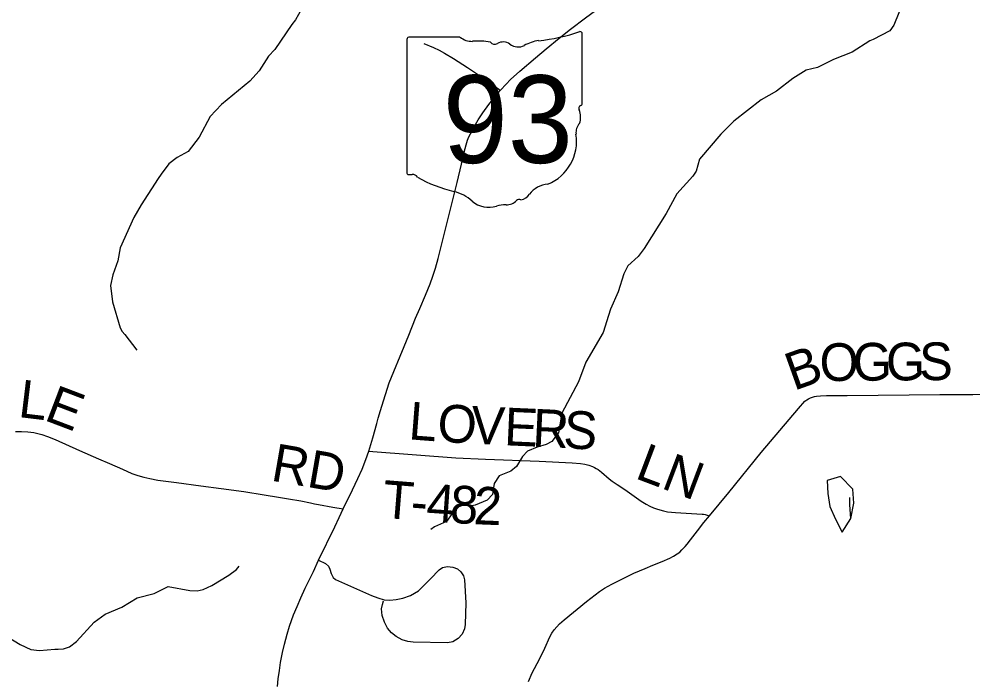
# Model space of a CAD drawing. Extents: x 0 to 34, y 0 to 22.
# Drawn here: x 2.781 to 4.217, y 16.645 to 17.641 of the extents above; entities that cross this region are included whole.
import ezdxf

# ---------------------------------------------------------------- set-up
doc = ezdxf.new("R2010")
doc.units = 0
for name, color, linetype in [('GM_X_County_Road', 7, 'Continuous'), ('GM_X_County_Road_Text', 7, 'Continuous'), ('GM_X_Minor_Lake', 7, 'Continuous'), ('GM_X_Minor_River', 7, 'Continuous'), ('GM_X_State_Location', 7, 'Continuous'), ('GM_X_State_Route', 7, 'Continuous'), ('GM_X_State_Shield', 7, 'Continuous'), ('GM_X_Township_Road', 7, 'Continuous'), ('GM_X_Township_Road_Text', 7, 'Continuous')]:
    doc.layers.add(name, color=color, linetype=linetype)

msp = doc.modelspace()

# ---------------------------------------------------------------- linework, layer by layer
at = {"layer": 'GM_X_County_Road'}
for points in [[(3.8202, 16.893), (3.8492, 16.9283), (3.8981, 16.9885), (3.9541, 17.0549), (3.9639, 17.0657), (3.9666, 17.0679), (3.9692, 17.0695), (3.9723, 17.0708), (3.9751, 17.0718), (3.978, 17.0726), (3.981, 17.0731), (3.9871, 17.0738), (3.9964, 17.0742), (4.0274, 17.0742), (4.1205, 17.0752), (4.167, 17.0757), (4.2167, 17.0758), (4.2456, 17.0761)], [(2.7753, 17.0201), (2.7846, 17.0199), (2.7937, 17.0194), (2.8028, 17.0184), (2.8088, 17.0172), (2.8148, 17.0157), (2.8236, 17.0128), (2.835, 17.0081), (2.8719, 16.9917), (2.9002, 16.9792), (2.9168, 16.972), (2.9362, 16.9632), (2.9506, 16.9571), (2.9594, 16.9539), (2.9684, 16.9513), (2.9775, 16.9492), (2.9898, 16.947), (3.0175, 16.9432), (3.0545, 16.9384), (3.0852, 16.9341), (3.1191, 16.9296), (3.1497, 16.925), (3.1712, 16.9215), (3.1865, 16.9189), (3.2048, 16.9156), (3.2196, 16.9126), (3.2256, 16.9113), (3.2316, 16.9102), (3.253, 16.9062), (3.2687, 16.9037)], [(3.5477, 16.644), (3.5534, 16.6568), (3.564, 16.6773), (3.5721, 16.6942), (3.5799, 16.711), (3.5828, 16.7164), (3.5863, 16.7214), (3.5902, 16.7261), (3.5945, 16.7305), (3.6014, 16.7368), (3.6351, 16.7643), (3.6546, 16.7792), (3.6622, 16.7843), (3.6729, 16.7905), (3.6839, 16.7961), (3.695, 16.8015), (3.7062, 16.8067), (3.7232, 16.8141), (3.7347, 16.8187), (3.749, 16.8245), (3.7605, 16.8295), (3.766, 16.8324), (3.7713, 16.8358), (3.7753, 16.8387), (3.7786, 16.8418), (3.7834, 16.8468), (3.7867, 16.8507), (3.7917, 16.8571), (3.802, 16.8706), (3.8118, 16.8829), (3.8202, 16.893)]]:
    msp.add_lwpolyline(points, dxfattribs=at)
at = {"layer": 'GM_X_Minor_Lake'}
for points in [[(4.0376, 16.9122), (4.0357, 16.9331), (4.0176, 16.9524), (3.9975, 16.9463), (3.9983, 16.9266), (4.0013, 16.9073), (4.0096, 16.8883), (4.0198, 16.8686), (4.0331, 16.889)], [(4.0376, 16.9122), (4.0357, 16.9331), (4.0176, 16.9524), (3.9975, 16.9463), (3.9983, 16.9266), (4.0013, 16.9073), (4.0096, 16.8883), (4.0198, 16.8686), (4.0331, 16.889), (4.0312, 16.9095), (4.0312, 16.9209)], [(4.0331, 16.889), (4.0376, 16.9122)]]:
    msp.add_lwpolyline(points, dxfattribs=at)
at = {"layer": 'GM_X_Minor_River'}
for points in [[(4.1128, 17.6687), (4.0975, 17.6315), (4.0915, 17.6231), (4.0666, 17.61), (4.0613, 17.6081), (4.0349, 17.5909), (4.007, 17.5801), (3.9828, 17.5678), (3.9658, 17.5639), (3.9454, 17.5513), (3.921, 17.5322), (3.8979, 17.5191), (3.8569, 17.4874), (3.8373, 17.4676), (3.8053, 17.4298), (3.8001, 17.4119), (3.7952, 17.4043), (3.7712, 17.3776), (3.755, 17.3483), (3.7216, 17.2957), (3.7126, 17.2835), (3.6972, 17.2694), (3.6912, 17.2576), (3.6826, 17.2302), (3.671, 17.2043), (3.668, 17.1948), (3.6598, 17.169), (3.634, 17.1244), (3.6228, 17.0951), (3.5977, 17.0479), (3.5929, 17.0179), (3.5827, 17.0053), (3.5741, 17.0004), (3.5605, 16.9965)], [(3.2057, 17.6558), (3.1967, 17.6398), (3.1915, 17.6326), (3.1659, 17.5952), (3.1562, 17.5849), (3.1423, 17.5628), (3.128, 17.5472), (3.0854, 17.5124), (3.0685, 17.4941), (3.0516, 17.4629), (3.0351, 17.4416), (3.0185, 17.4324), (3.0064, 17.4232), (2.9944, 17.4076), (2.9899, 17.4007), (2.9647, 17.3615), (2.9535, 17.3424), (2.9329, 17.2964), (2.9292, 17.277), (2.9221, 17.2561), (2.9184, 17.2401), (2.9212, 17.2151), (2.9327, 17.1761), (2.9358, 17.1708), (2.94, 17.1659), (2.9579, 17.1424)], [(3.5605, 16.9965), (3.5461, 16.9903), (3.5386, 16.9823), (3.5296, 16.9675), (3.5209, 16.9606), (3.5036, 16.9533), (3.4961, 16.9419), (3.4935, 16.9251), (3.4852, 16.9167), (3.4671, 16.9091), (3.4622, 16.9083), (3.4569, 16.9086), (3.4482, 16.9086), (3.4429, 16.9066), (3.4327, 16.8967), (3.4241, 16.8849), (3.4063, 16.8768), (3.4007, 16.8726)], [(2.7481, 16.7203), (2.7823, 16.6996), (2.7986, 16.6921), (2.8115, 16.6907), (2.8345, 16.6927), (2.8395, 16.6927), (2.8478, 16.6928), (2.8565, 16.6962), (2.867, 16.7039), (2.8937, 16.7329), (2.9103, 16.7451), (2.9352, 16.7559), (2.9586, 16.7697), (2.9843, 16.7762), (3.0054, 16.787), (3.038, 16.7807), (3.049, 16.7804), (3.058, 16.7823), (3.0709, 16.7881), (3.0965, 16.8038), (3.1078, 16.8126), (3.112, 16.8175)]]:
    msp.add_lwpolyline(points, dxfattribs=at)
at = {"layer": 'GM_X_State_Route'}
for points in [[(3.5584, 17.5825), (3.5744, 17.5962), (3.5936, 17.6121), (3.611, 17.6257), (3.6337, 17.6425), (3.6562, 17.6591), (3.6791, 17.6754), (3.6917, 17.684), (3.7071, 17.6945), (3.7281, 17.7079), (3.7397, 17.7153), (3.7516, 17.7229), (3.7778, 17.7397), (3.7987, 17.7531), (3.8221, 17.7683), (3.8353, 17.7765), (3.8541, 17.7875), (3.8895, 17.8069), (3.9169, 17.8215), (3.9196, 17.823)], [(3.3193, 17.0323), (3.3215, 17.04), (3.3248, 17.0516), (3.3292, 17.0664), (3.3323, 17.076), (3.338, 17.0932), (3.345, 17.1105), (3.3544, 17.1335), (3.3604, 17.1478), (3.3639, 17.1564), (3.3673, 17.165), (3.3777, 17.1909), (3.3838, 17.2051), (3.3924, 17.2251), (3.3994, 17.2423), (3.4036, 17.254), (3.4074, 17.2658), (3.4116, 17.2807), (3.4254, 17.3348), (3.44, 17.395), (3.4467, 17.4227), (3.451, 17.4405), (3.454, 17.4517), (3.456, 17.4584), (3.458, 17.4635), (3.4601, 17.468), (3.4658, 17.4785), (3.4721, 17.489), (3.4788, 17.4998), (3.488, 17.5125), (3.4975, 17.5245), (3.505, 17.5333), (3.5056, 17.534), (3.5141, 17.5431), (3.5207, 17.5497), (3.5347, 17.5624), (3.5584, 17.5825)], [(3.1697, 16.6365), (3.171, 16.648), (3.1727, 16.6603), (3.1743, 16.6725), (3.1775, 16.6875), (3.1802, 16.7001), (3.1842, 16.7151), (3.1878, 16.7273), (3.194, 16.7444), (3.1993, 16.7569), (3.2048, 16.7696), (3.2116, 16.7842), (3.2238, 16.8093), (3.2315, 16.8265), (3.2561, 16.8764), (3.2624, 16.8905), (3.2687, 16.9037), (3.2827, 16.9325), (3.2907, 16.9493), (3.297, 16.9634), (3.3027, 16.9778), (3.3071, 16.9904), (3.3088, 16.9954), (3.3131, 17.0104), (3.3193, 17.0323)]]:
    msp.add_lwpolyline(points, dxfattribs=at)
at = {"layer": 'GM_X_State_Shield'}
for p, q in [((3.3647, 17.6103), (3.3647, 17.4101)), ((3.4445, 17.6137), (3.3673, 17.6137)), ((3.6284, 17.514), (3.6284, 17.6187)), ((3.6283, 17.514), (3.6284, 17.514))]:
    msp.add_line(p, q, dxfattribs=at)
for centre, radius, start, end in [((3.5344, 17.8865), 0.2796, 275.8445, 288.9065), ((3.6254, 17.6191), 0.00294, 351.8621, 97.738), ((3.3677, 17.6107), 0.00305, 98.1301, 188.1301), ((3.4629, 17.6369), 0.0296, 231.6195, 271.1119), ((3.4727, 17.5014), 0.1064, 80.4867, 94.9883), ((3.4969, 17.6117), 0.00855, 219.7921, 297.1024), ((3.5094, 17.5886), 0.0178, 54.4667, 119.1411), ((3.5701, 17.5526), 0.0563, 97.3462, 120.7689), ((3.5324, 17.6203), 0.0214, 233.8562, 294.8282), ((3.6277, 17.5063), 0.00454, 107.944, 210.337), ((3.6252, 17.5136), 0.00314, 289.6038, 7.7341), ((3.5988, 17.4931), 0.0273, 340.033, 23.6496), ((3.6389, 17.4702), 0.0198, 136.8065, 186.9296), ((3.5501, 17.4569), 0.0699, 292.3089, 8.9858), ((3.3677, 17.4097), 0.00308, 171.9584, 258.3066), ((3.3682, 17.4302), 0.0235, 267.339, 280.6039), ((3.373, 17.3986), 0.00848, 29.7484, 93.2717), ((3.4801, 17.5784), 0.2019, 240.4129, 257.1985), ((3.5796, 17.354), 0.0383, 94.4031, 142.5768), ((3.4199, 17.3202), 0.0632, 47.1842, 75.836), ((3.5311, 17.3907), 0.0226, 282.8732, 323.2771), ((3.4882, 17.3976), 0.0401, 230.7004, 286.2918), ((3.5114, 17.3284), 0.0329, 85.6951, 111.2099), ((3.5143, 17.3826), 0.0214, 268.777, 315.5493), ((3.5336, 17.3632), 0.00601, 65.7517, 132.6484)]:
    msp.add_arc(centre, radius, start, end, dxfattribs=at)
at = {"layer": 'GM_X_Township_Road'}
for points in [[(3.3901, 17.6043), (3.4045, 17.5983), (3.4129, 17.5942), (3.4212, 17.5897), (3.4345, 17.5814), (3.4556, 17.5679), (3.474, 17.5561), (3.4922, 17.5437), (3.4977, 17.5395), (3.5028, 17.5352), (3.505, 17.5333)], [(3.3071, 16.9904), (3.3133, 16.9899), (3.4383, 16.9807), (3.4827, 16.9785), (3.5635, 16.9755), (3.6133, 16.973), (3.6259, 16.9719), (3.6324, 16.9708), (3.6383, 16.9693), (3.6441, 16.9673), (3.6468, 16.9661), (3.6497, 16.9645), (3.6525, 16.9627), (3.6575, 16.9589), (3.6693, 16.9489), (3.6737, 16.9455), (3.6813, 16.9402), (3.6927, 16.9327), (3.7174, 16.9154), (3.725, 16.9106), (3.7304, 16.9077), (3.736, 16.9051), (3.7418, 16.9031), (3.7508, 16.9005), (3.7568, 16.8993), (3.7629, 16.8985), (3.7691, 16.898), (3.8093, 16.8958), (3.811, 16.8955), (3.8135, 16.8951), (3.8167, 16.8943), (3.8202, 16.893)], [(3.2315, 16.8265), (3.2421, 16.8213), (3.2463, 16.8175), (3.2486, 16.8128), (3.2504, 16.8064), (3.2537, 16.8006), (3.2573, 16.7974), (3.3115, 16.7733), (3.3208, 16.7698), (3.3301, 16.7669)], [(3.3301, 16.7669), (3.3391, 16.7664), (3.3485, 16.7671), (3.3587, 16.7693), (3.3701, 16.7733), (3.3818, 16.7803), (3.3908, 16.7887), (3.4002, 16.7986), (3.413, 16.8121), (3.4181, 16.8153), (3.4255, 16.8168), (3.4335, 16.8158), (3.4408, 16.8133), (3.4457, 16.8089), (3.4496, 16.8031), (3.4513, 16.7968), (3.4535, 16.7621), (3.4524, 16.7296), (3.4514, 16.7229), (3.448, 16.7153), (3.4419, 16.7086), (3.4335, 16.7036), (3.4258, 16.7019), (3.3742, 16.7029), (3.3659, 16.704), (3.3574, 16.7064), (3.3483, 16.7114), (3.3416, 16.7171), (3.3356, 16.724), (3.3306, 16.7329), (3.3273, 16.7434), (3.3265, 16.7532), (3.3276, 16.7599), (3.3291, 16.765)]]:
    msp.add_lwpolyline(points, dxfattribs=at)

# ---------------------------------------------------------------- texts
at = {"layer": 'GM_X_County_Road_Text'}
for s, height, rotation, p in [('B', 0.0568, 19.6853, (3.947, 17.081)), ('O', 0.0568, 0.6812, (3.9861, 17.0958)), ('G', 0.0568, 0.4444, (4.036, 17.0964)), ('G', 0.0568, 0.4486, (4.086, 17.0968)), ('S', 0.0568, 0.4479, (4.136, 17.0972)), ('L', 0.0568, 353.0919, (2.7782, 17.0421)), ('E', 0.0568, 339.1656, (2.8168, 17.0379)), ('RD', 0.05682, 350.1333, (3.1583, 16.9465))]:
    msp.add_text(s, height=height, rotation=rotation, dxfattribs=at).set_placement(p)
at = {"layer": 'GM_X_State_Location'}
for s in ['s', 'r']:
    msp.add_text(s, height=0.000189, dxfattribs=at).set_placement((3.4936, 17.4969))
msp.add_text('93', height=0.000189, rotation=0, dxfattribs=at).set_placement((3.4459, 17.4831))
at = {"layer": 'GM_X_State_Shield'}
msp.add_text('93', height=0.13184, dxfattribs=at).set_placement((3.4184, 17.4243))
at = {"layer": 'GM_X_Township_Road_Text'}
for s, height, rotation, p in [('L', 0.0568, 355.5816, (3.366, 17.0085)), ('O', 0.0568, 356.3406, (3.4092, 17.0051)), ('V', 0.0568, 357.2959, (3.4601, 17.0019)), ('E', 0.0568, 357.4499, (3.5102, 16.9995)), ('R', 0.0568, 357.3958, (3.5527, 16.9976)), ('S', 0.0568, 356.2959, (3.599, 16.9955)), ('LN', 0.05682, 339.2607, (3.7063, 16.9504)), ('T', 0.0568, 355.4439, (3.3263, 16.8904)), ('4', 0.0568, 356.0949, (3.3927, 16.8852)), ('8', 0.0568, 356.8189, (3.4284, 16.8827)), ('2', 0.0568, 357.7112, (3.4643, 16.8807)), ('-', 0.0568, 355.6118, (3.3689, 16.887))]:
    msp.add_text(s, height=height, rotation=rotation, dxfattribs=at).set_placement(p)

doc.saveas('drawing.dxf')
